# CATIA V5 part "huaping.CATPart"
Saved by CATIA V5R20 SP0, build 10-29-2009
Part number: 花瓶
Material "DS star": density 1000 kg/m3
Material "Bordeaux Red": density 7860 kg/m3, Young's modulus 2e+11 Pa, Poisson ratio 0.266
Material "Steel": density 7860 kg/m3, Young's modulus 2e+11 Pa, Poisson ratio 0.266, thermal expansion 1.17e-05 1/K
Bounding box of the stored display mesh (mm): x -46.554 to 34.061, y -34.045 to 34.01, z -0.166 to 79.03
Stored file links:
  E:\3d\侯博文\huaping.CATPart
  E:\CATIA\win_b64\startup\materials\Catalog.CATMaterial
  E:\CATIA\win_b64\startup\materials\honeycomb.jpg
  E:\CATIA\win_b64\startup\materials\DS_star.jpg
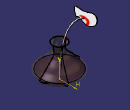
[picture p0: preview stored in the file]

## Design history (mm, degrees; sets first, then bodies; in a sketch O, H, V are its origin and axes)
Body1 (main body), material "Steel"
  Plane1: type Offset, RefPlane xy-plane, Offset 15
  Plane2: type Offset, RefPlane Plane1, Offset 9
  Plane3: type Offset, RefPlane Plane2, Offset 20
  Plane4: type Offset, RefPlane Plane3, Offset 11
  Sketch1 on xy-plane, origin (0, 0, 0), H (1, 0, 0), V (0, 1, 0)
    circle A1 centre (0, 0) radius 10
  Sketch2 on Plane1, origin (0, 0, 15), H (1, 0, 0), V (0, 1, 0)
    circle A1 centre (0, 0) radius 34.0606
  Sketch3 on Plane2, origin (0, 0, 24), H (1, 0, 0), V (0, 1, 0)
    circle A1 centre (0, 0) radius 25.1206
  Sketch4 on Plane3, origin (0, 0, 44), H (1, 0, 0), V (0, 1, 0)
    circle A1 centre (0, 0) radius 9.9467
  Sketch5 on Plane4, origin (0, 0, 55), H (1, 0, 0), V (0, 1, 0)
    circle A1 centre (0, 0) radius 12.0139
  Loft1: solid, Sections (Sketch1; Sketch2; Sketch3; Sketch4; Sketch5)
  Shell1: IntOffset 1, Face face of Loft1, ExtOffset 0
  Sketch6 on yz-plane, origin (0, 0, 0), H (0, 1, 0), V (0, 0, 1)
Body2, material "DS star"
  Sketch7 on zx-plane, origin (0, 0, 0), H (-1, 0, 0), V (0, 0, 1)
    spline S1 through (3.3521, 0) (2.4496, 34.6996) (21.7885, 71.3313) (42.0298, 69.0178)
    point P1 (3.3521, 0)
    coincidence: P1 H
  Plane5: type Normal, Curve Sketch7, RefPoint vertex of Sketch7
  Sketch8 on Plane5, origin (-7.7283, 0, -3.6481), H (0, 1, 0), V (-0.4269, 0, 0.9043)
    spline S1 through (-11.9026, 77.0612) (-17.9079, 87.782) (1.9234, 88.4781) (16.0288, 90.1489) (21.0564, 84.3012) (5.5545, 74.4158) (-6.037, 78.3143) (-11.9026, 77.0612)
    point P1 (-11.9026, 77.0612)
    point P2 (-11.9026, 77.0612)
    coincidence: P1 P2
  Pad1: profile Sketch8, direction (0.9043, 0, 0.4269), length 1
  Sketch9 on Plane5, origin (-7.7283, 0, -3.6481), H (0, 1, 0), V (-0.4269, 0, 0.9043)
    circle A1 centre (0, 80) radius 1
    point P1 (0, 80)
    radius A1 = 1
    coincidence: P1 V
  Rib1: profile Sketch9, centre curve Sketch7
Body3, material "Bordeaux Red"
  Sketch10 on zx-plane, origin (0, 0, 0), H (-1, 0, 0), V (0, 0, 1)
    axis line L1 (0, 72.4224) -> (0, -20.0672)
    point P1 (0, 72.4224)
    line L2 (0, 15.1062) -> (31.1387, 15.1062)
    point P3 (0, 15.1062)
    arc A1 centre (2.67, 38.2759) radius 36.7056 from (31.1387, 15.1062) to (0, 1.6675) cw
    point P6 (0, 1.6675)
    coincidence: P1 V, P3 L1, P6 L1
    vertical: L1 V
    horizontal: L2 H
  Shaft1: profile Sketch10, axis Sketch10.L1, angle 360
